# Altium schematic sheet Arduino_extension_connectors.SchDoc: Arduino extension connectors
size A4; Date: Not used; ApprovedBy: Not used; CheckedBy: Not used; Author: Not used; CompanyName: STMicroelectronics; DrawnBy: Not used; Engineer: Not used; Organization: Not used; Address1: Not used; Address2: Not used; Address3: Not used; Address4: Not used; DocumentNumber: Not used; Revision: Not used; SheetNumber: 6; SheetTotal: 7
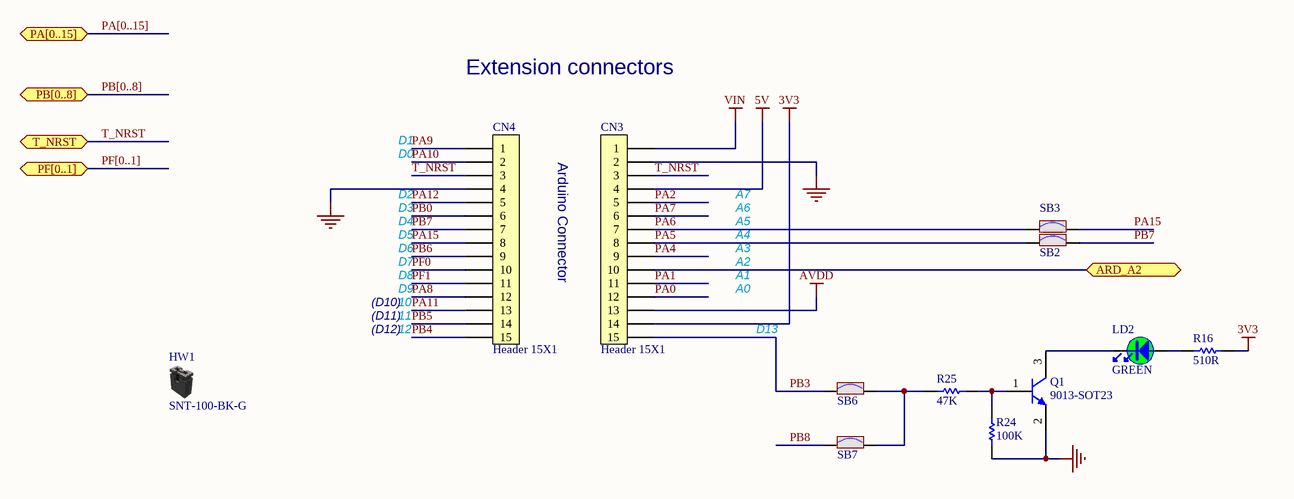
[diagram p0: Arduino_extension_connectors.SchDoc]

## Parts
CN3  value Header 15X1  [CON_LYCN_313115S161145]
CN4  value Header 15X1  [CON_LYCN_313115S161145]
HW1  value SNT-100-BK-G  (hidden comment: Shunt Black 2.54mm)  (mechanical)
LD2  value GREEN  [LED_0603_GREEN]
Q1  value 9013-SOT23  [NPN_SOT23]
R16  value 510R  [R0402]
R24  value 100K  [R0402]
R25  value 47K  [R0402]
SB2  (no value)  [SOLDER-BRIDGE_R0603-0R]
SB3  (no value)  [SOLDER-BRIDGE_R0603-0R]
SB6  (no value)  [SOLDER-BRIDGE_R0603-0R]
SB7  (no value)  [SOLDER-BRIDGE_R0603-0R]

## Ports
ARD_A2, PA[0..15] (bidir), PB[0..8] (bidir), PF[0..1] (bidir), T_NRST

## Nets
3V3: CN3.14 R16.2
5V: CN3.4
AVDD: CN3.13
GND: CN3.2 CN4.4 Q1.2(E) R24.1
VIN: CN3.1
ARD_A2: CN3.10 ; port ARD_A2
PA0: CN3.12
PA1: CN3.11
PA2: CN3.5
PA4: CN3.9
PA5: CN3.8 SB2.1
PA6: CN3.7 SB3.1
PA7: CN3.6
PA8: CN4.12
PA9: CN4.1
PA10: CN4.2
PA11: CN4.13
PA12: CN4.5
PA15: CN4.8 SB3.2
PB0: CN4.6
PB3: CN3.15 SB6.1
PB4: CN4.15
PB5: CN4.14
PB6: CN4.9
PB7: CN4.7 SB2.2
PB8: SB7.1
PF0: CN4.10
PF1: CN4.11
T_NRST: CN3.3 CN4.3 ; port T_NRST
NetLD2_1: LD2.1 R16.1
NetLD2_2: LD2.2 Q1.3(C)
NetQ1_1: Q1.1(B) R24.2 R25.2
NetR25_1: R25.1 SB6.2 SB7.2

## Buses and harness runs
bus PA[0..15] = port PA[0..15]
bus PB[0..8] = port PB[0..8]
bus PF[0..1] = port PF[0..1]

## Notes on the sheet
- Extension connectors
- D0
- D1
- D2
- Arduino Connector
- A7
- D4
- D3
- D5
- D6
- D7
- A2
- A3
- A4
- A5
- A6
- (D10)
- (D12)
- (D11)
- D8
- D9
- 10
- 12
- 11
- A0
- A1
- D13

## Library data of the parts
CN3 CN4 = MCD-01332: Pin header, 15x1, 2,54mm, VR, TH, Height 6mm/6mm; Part_Type: Connector; Manufacturer_Part_Number: 313115S161145; Manufacturer: LYCN; Provided_By: SUBCO; Initial_Board_Reference: tbd; Remark: Official footprint by subcon done.
HW1 = MCD-00043: SHUNT 2.54mm BLACK; Part_Type: Mechanical; Manufacturer: SAMTEC; Provided_By: SUBCO
LD2 = MCD-00050: LED, Green, 0603; Manufacturer_Part_Number: 19-213SYGC/S530-E2/TR8; Manufacturer: EVERLIGHT; Part_Type: Display; Provided_By: SUBCO; Initial_Board_Reference: MB1274
Q1 = MCD-00073: NPN Bipolar Transistor; Part_Type: IC; Manufacturer_Part_Number: BSR14; Manufacturer: NXP; Provided_By: SUBCO; Initial_Board_Reference: MB1274
R16 = MCD-00064: Resistor,510R,0402,1%,1/16W; Manufacturer_Part_Number: RC0402FR-07510RL; Manufacturer: YAGEO; Provided_By: SUBCO; Initial_Board_Reference: MB1274
R24 = MCD-00059: Resistor,100K,0402,1%,1/16W; Manufacturer_Part_Number: RC0402FR-07100KL; Manufacturer: YAGEO; Alternate_Manufacturer_Part_Number: RT0402FRE07100KL; Provided_By: SUBCO; Initial_Board_Reference: MB1274
R25 = MCD-00063: Resistor,47K,0402,1%,1/16W; Manufacturer_Part_Number: RC0402FR-0747KL; Manufacturer: YAGEO; Provided_By: SUBCO; Initial_Board_Reference: MB1274
SB2 SB3 SB6 SB7 = MCD-00071: Solder Bridge ON; Part_Type: Mechanical; Manufacturer_Part_Number: RC0603JR-070RL; Manufacturer: YAGEO; Provided_By: SUBCO; Initial_Board_Reference: MB1274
